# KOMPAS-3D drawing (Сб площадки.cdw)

Views: Вид 1, Вид 2
Referenced files in C:\Documents and Settings\Конструктор\Мои документы\Архив чертежей\ММТ-инжиниринг\Бункер 6м3\Площадка обслуживания\: Сб площадки.cdw
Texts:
  Площадка обслуживания Сборочный чертёж
  Филиппова Т.В.
  ООО "ХСМ"
  Деталь поз3  L=490
  Деталь поз5  L=1515
  *Размер для справок.
  Сварка по ГОСТ1471-76.
  Перекладина
  Лист ПВ1 406 ТУ36.26.11-5-89
  Ст3сп ГОСТ380-88
  Уголок
  ГОСТ
  Ст2сп
  Уголок  50х50х5-В ГОСТ 8509-93 Ст3пс3-1 ГОСТ 535-88
  Уголок $d50х50х5-В ГОСТ 8509-93;Ст3пс3-1 ГОСТ 535-88$
  Швеллер  №12  ГОСТ 8240-97 Ст3пс3-1 ГОСТ 535-88
  Швеллер $d№12  ГОСТ 8240-97;Ст3пс3-1 ГОСТ 535-88$
  Связь
  Площадка обслуживания
  Сборочный чертёж
Dimensions and other numbers on the sheet: 1500; 1880*; 500; 120*; 750; 1; 2; 3; 4; 5; 6; 398; 300; 47; 98; 1490; 50х50х5*; 86; 88; 2,8 м; 2,8 м@129~; 1:10; 153; 0; 7; 8; 9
